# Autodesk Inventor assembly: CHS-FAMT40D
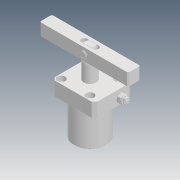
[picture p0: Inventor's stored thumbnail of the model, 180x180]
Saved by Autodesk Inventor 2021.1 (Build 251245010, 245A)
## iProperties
Created: 2019-05
Part Number: CHS-FAMT40D
Description: STEP AP203
Document SubType Name: Assembly
Designer: user
Title: chs-famt40d_asm.STEP
Revision Number: ÈÎºÎ
Sending System: SolidWorks 2017
Preprocessor: SwSTEP 2.0
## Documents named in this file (7)
- D:\Vault_2016\Projekty\Clamptek\Hydraulic\CHS\CHS-40\Inventor\CHS-FAMT40D\CHS-FAMT40D.iam
- D:\Vault_2016\Projekty\Clamptek\Hydraulic\CHS\CHS-40\Inventor\CHS-FAMT40D\CHS-FAMT40-03.ipt
- D:\Vault_2016\Projekty\Clamptek\Hydraulic\CHS\CHS-40\Inventor\CHS-FAMT40D\CHS-40D-02_3.ipt
- D:\Vault_2016\Projekty\Clamptek\Hydraulic\CHS\CHS-40\Inventor\CHS-FAMT40D\CHS-40D-01_4.ipt
- D:\Vault_2016\Projekty\Clamptek\Hydraulic\CHS\CHS-40\Inventor\CHS-FAMT40D\XIAO.ipt
- D:\Vault_2016\Projekty\Clamptek\Hydraulic\CHS\CHS-40\Inventor\CHS-FAMT40D\12ÖáÓÃµ²È¦.ipt
- D:\Vault_2016\Projekty\Clamptek\Hydraulic\CHS\CHS-40\Inventor\CHS-FAMT40D\CZL10µ÷ËÙ·§_1.ipt
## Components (7 placed, 7 different names)
1. CHS-FAMT40-03_1
2. CHS-40D-02_3_2
3. CHS-40D-01_4_3
4. XIAO_4
5. 12ÖáÓÃµ²È¦_5
6. CZL10µ÷ËÙ·§_1_6
7. 12ÖáÓÃµ²È¦_7
